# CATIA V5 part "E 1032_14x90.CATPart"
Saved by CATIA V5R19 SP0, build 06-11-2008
Nomenclature: E 1032_14x90
Description: PART-E 1032_14x90-DESC
Property "Hersteller": "Meusburger"
Property "Material": "1.7131 ~ 60 HRC"
Property "Bestellnummer": "E 1032/14x90"
Property "Teilenummer": "E 1032/14x90"
Property "Beschreibung": "Schrägbolzen mit konischem Bund _ Inclined pin with tapered collar"
Material "Steel": density 7860 kg/m3, Young's modulus 2e+11 Pa, Poisson ratio 0.266, thermal expansion 1.17e-05 1/K
Bounding box of the stored display mesh (mm): x -8.5 to 8.5, y -8.49 to 8.49, z 0 to 90
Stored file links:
  G:\UTB\Kombinované\Bakalářská práce\Catia\FORMA\E 1032_14x90.CATPart
  D:\Aplikace\CATIA\Nová složka\win_b64\startup\materials\Catalog.CATMaterial
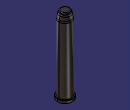
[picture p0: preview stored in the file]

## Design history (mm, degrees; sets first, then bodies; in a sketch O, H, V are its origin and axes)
Set1
  DatumSurface1 "CLOSED_SHELL #140"
  Loft1: Sections (edge of DatumSurface1; edge of DatumSurface1)
  Loft2: Sections (edge of DatumSurface1; edge of DatumSurface1)
Body1 (main body)
  Join1: Elements (DatumSurface1; Loft1; Loft2)
  CloseSurface1: CloseElement Join1
  Fillet1: radius 10, on edge [face of CloseSurface1 | face of CloseSurface1]
  Fillet2: radius 10, on edge [face of CloseSurface1 | face of CloseSurface1]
